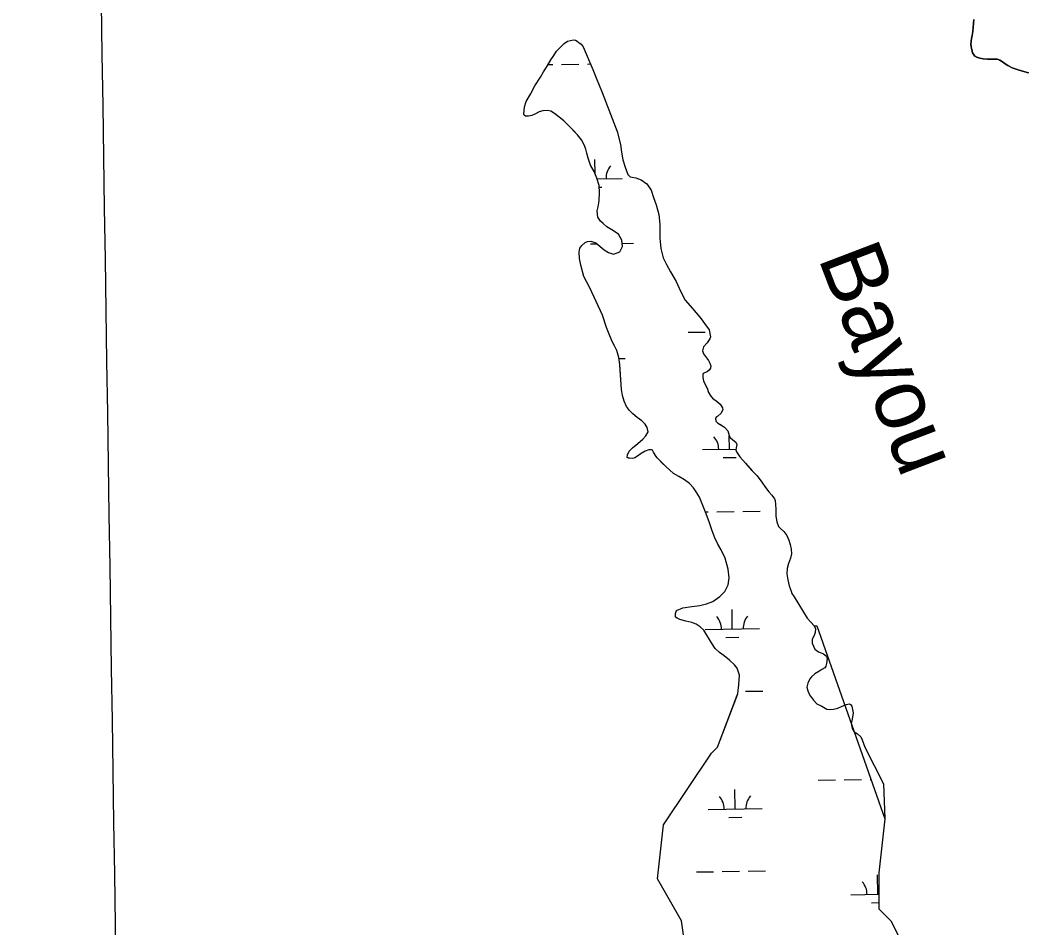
# Model space of a CAD drawing. Extents: x 3823584 to 3861785, y 301729 to 327625.
# Drawn here: x 3832860 to 3834718, y 313764 to 315442 of the extents above; entities that cross this region are included whole.
import ezdxf

# ---------------------------------------------------------------- set-up
doc = ezdxf.new("R2010")
doc.units = 0
for name, color, linetype in [('V-GRID-MAJR', 7, 'Continuous'), ('V-RIVR-IDEN', 7, 'Continuous'), ('V-TOPO-SHOR', 7, 'Continuous'), ('V-WETL-SWMP', 7, 'Continuous')]:
    doc.layers.add(name, color=color, linetype=linetype)

msp = doc.modelspace()

# ---------------------------------------------------------------- linework, layer by layer
at = {"layer": 'V-GRID-MAJR'}
msp.add_spline([(3833134.7290000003, 307237.467), (3833043.082, 313295.662), (3832951.406, 319355.783), (3832859.73, 325415.89900000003), (3832859.701, 325417.829)], degree=3, dxfattribs=at)
at = {"layer": 'V-TOPO-SHOR'}
for p, q in [((3834148.2605254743, 314097.8889411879), (3834184.037966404, 314191.527087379)), ((3834048.736592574, 313954.03293367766), (3834137.202533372, 314086.8229403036)), ((3834137.202533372, 314086.8229403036), (3834148.2605254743, 314097.8889411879)), ((3834455.48, 314029.759), (3834457.89626447, 313965.09997039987)), ((3834037.6785925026, 313854.43893368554), (3834048.736592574, 313954.03293367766)), ((3834457.89626447, 313965.09997039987), (3834446.8382643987, 313865.50697040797)), ((3834446.8382643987, 313865.50697040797), (3834446.838258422, 313799.11197107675)), ((3834081.9115499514, 313776.97793844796), (3834037.6785925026, 313854.43893368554)), ((3834446.838258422, 313799.11197107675), (3834468.954238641, 313776.97997329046)), ((3834092.9695340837, 313699.51694022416), (3834081.9115499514, 313776.97793844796)), ((3834468.954238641, 313776.97997329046), (3834491.0702168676, 313732.71597572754))]:
    msp.add_line(p, q, dxfattribs=at)
for points in [[(3834622.359, 315443.34), (3834621.632, 315435.681), (3834620.434, 315421.416), (3834619.183, 315413.48600000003), (3834618.171, 315408.2), (3834617.157, 315403.177), (3834616.9420000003, 315397.367), (3834617.796, 315390.248), (3834618.898, 315384.714), (3834619.717, 315381.554), (3834622.9220000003, 315377.093), (3834624.253, 315375.78500000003), (3834627.969, 315373.442), (3834633.2630000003, 315371.64), (3834639.341, 315370.634), (3834647.267, 315369.909), (3834653.335, 315370.224), (3834659.4050000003, 315370.278), (3834665.744, 315369.803), (3834670.247, 315367.994), (3834675.29, 315364.869), (3834680.332, 315361.482), (3834684.846, 315358.352), (3834693.328, 315354.201), (3834702.0670000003, 315350.842), (3834712.387, 315347.764), (3834723.235, 315344.688)], [(3833912.264, 314947.337), (3833901.623, 314967.917), (3833895.686, 314989.321), (3833893.486, 315001.601), (3833893.128, 315013.11100000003), (3833894.375, 315020.449), (3833897.992, 315025.712), (3833903.704, 315030.994), (3833908.133, 315033.124), (3833914.671, 315033.703), (3833923.598, 315030.115), (3833939.14, 315017.69), (3833947.295, 315012.525), (3833956.481, 315009.463), (3833968.216, 315014.012), (3833973.106, 315023.471), (3833971.6950000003, 315035.495), (3833965.326, 315046.169), (3833953.218, 315054.439), (3833944.012, 315060.118), (3833936.898, 315066.076), (3833932.148, 315070.745), (3833927.376, 315078.03), (3833925.969, 315089.532), (3833928.001, 315096.876), (3833929.74, 315107.88), (3833930.653, 315123.588), (3833930.02, 315136.402), (3833925.715, 315150.234), (3833920.38, 315162.22500000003), (3833913.741, 315173.942), (3833909.182, 315186.726), (3833907.271, 315196.128), (3833905.377, 315203.702), (3833902.168, 315211.78500000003), (3833897.1210000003, 315220.63800000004), (3833889.9760000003, 315229.998), (3833881.528, 315238.82300000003), (3833872.818, 315247.906), (3833864.376, 315255.946), (3833855.68, 315262.936), (3833846.988, 315269.666), (3833840.674, 315273.798), (3833833.599, 315275.04600000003), (3833825.4930000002, 315274.454), (3833818.705, 315272.566), (3833811.1520000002, 315268.576), (3833805.156, 315265.907), (3833799.413, 315264.29), (3833793.654, 315264.503), (3833791.023, 315266.313), (3833790.4820000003, 315268.4), (3833791.6780000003, 315281.755), (3833794.994, 315291.727), (3833802.7290000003, 315305.137), (3833810.708, 315320.902), (3833821.562, 315336.695), (3833827.235, 315346.425), (3833833.949, 315357.20900000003), (3833840.65, 315369.041), (3833845.8170000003, 315376.934), (3833851.2460000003, 315384.569), (3833858.764, 315392.744), (3833865.252, 315399.079), (3833871.4990000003, 315403.058), (3833882.204, 315405.76300000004), (3833885.87, 315405.272), (3833889.288, 315403.47000000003), (3833892.452, 315400.619), (3833896.665, 315397.514), (3833900.103, 315393.094), (3833918.253, 315351.123), (3833924.143, 315335.474), (3833935.6240000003, 315308.358), (3833963.186, 315236.375), (3833969.4080000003, 315212.356), (3833971.363, 315197.719), (3833973.835, 315184.135), (3833977.6180000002, 315170.039), (3833982.961, 315157.001), (3833987.184, 315152.588), (3833990.59, 315152.094), (3833997.406, 315150.843), (3834007.379, 315147.003), (3834017.648, 315139.503), (3834025.6010000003, 315127.534), (3834030.4220000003, 315114.493), (3834034.984, 315100.925), (3834039.848, 315082.65), (3834042.091, 315065.13800000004), (3834042.1890000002, 315053.626), (3834041.79, 315038.971), (3834044.049, 315019.627), (3834048.378, 315002.656), (3834053.98, 314990.14400000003), (3834061.42, 314976.601), (3834072.301, 314958.64), (3834080.3030000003, 314940.914), (3834088.816, 314924.242), (3834102.294, 314908.656), (3834109.163, 314900.866)], [(3834184.037966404, 314191.527087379), (3834185.793, 314196.876), (3834188.009, 314213.117), (3834188.906, 314230.918), (3834184.6070000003, 314243.964), (3834180.108, 314250.206), (3834170.873, 314259.023), (3834160.603, 314266.787), (3834151.915, 314272.992), (3834144.2660000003, 314280.252), (3834137.112, 314290.658), (3834123.046, 314314.087), (3834116.7120000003, 314320.575), (3834109.345, 314325.222), (3834100.946, 314328.29), (3834090.194, 314331.077), (3834079.1780000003, 314334.125), (3834073.667, 314336.17100000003), (3834070.769, 314338.501), (3834070.9760000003, 314344.783), (3834072.7600000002, 314350.554), (3834084.231, 314355.623), (3834101.217, 314358.121), (3834115.852, 314360.077), (3834128.39, 314362.801), (3834139.865, 314367.085), (3834152.869, 314376.355), (3834162.21, 314385.591), (3834168.123, 314397.938), (3834170.1070000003, 314410.777), (3834168.397, 314427.24700000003), (3834162.468, 314447.607), (3834155.54, 314462.463), (3834149.169, 314473.135), (3834143.311, 314484.86), (3834138.757, 314497.641), (3834133.119, 314514.341), (3834126.4220000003, 314532.601), (3834120.273, 314547.985), (3834115.201, 314559.978), (3834109.36, 314569.87), (3834104.061, 314577.415), (3834096.93, 314585.203), (3834087.45, 314592.449), (3834077.196, 314598.38), (3834067.468, 314603.791), (3834059.56, 314610.527), (3834053.494, 314616.233), (3834045.843, 314623.755), (3834039.775, 314629.723), (3834036.8710000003, 314632.576), (3834033.954, 314636.999), (3834030.4990000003, 314643.512), (3834028.115, 314646.893), (3834026.8030000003, 314647.405), (3834021.83, 314647.362), (3834014.787, 314644.94800000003), (3834007.2320000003, 314640.958), (3834000.472, 314635.93), (3833995.526, 314633.01), (3833993.961, 314632.473), (3833991.614, 314631.406), (3833986.113, 314632.146), (3833984.282, 314632.129), (3833983.494, 314632.645), (3833981.653, 314633.678), (3833981.876, 314638.128), (3833985.22, 314644.958), (3833991.708, 314651.032), (3834001.322, 314659.224), (3834010.411, 314667.412), (3834016.112, 314673.741), (3834020.4990000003, 314681.105), (3834018.336, 314689.199), (3834014.8850000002, 314694.925), (3834008.551, 314701.413), (3834000.128, 314707.358), (3833991.958, 314714.092), (3833985.89, 314720.058), (3833980.332, 314727.601), (3833976.059, 314737.507), (3833972.832, 314747.946), (3833970.903, 314759.441), (3833969.7, 314777.748), (3833968.775, 314794.224), (3833968.1580000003, 314805.21), (3833966.217, 314818.27400000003), (3833962.182, 314831.06200000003), (3833958.18, 314840.186), (3833954.461, 314846.696), (3833949.392, 314858.165), (3833943.502, 314873.816), (3833935.72, 314896.77400000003), (3833912.264, 314947.337)], [(3834109.163, 314900.866), (3834112.6, 314896.708), (3834118.156, 314889.69), (3834124.247, 314881.107), (3834132.9790000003, 314869.406), (3834135.707, 314856.346), (3834134.429, 314852.672), (3834129.52, 314845.306), (3834122.5160000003, 314838.181), (3834120.486, 314830.837), (3834122.627, 314825.36), (3834126.3310000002, 314820.42), (3834131.628, 314812.878), (3834134.286, 314808.19), (3834136.16, 314803.23600000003), (3834135.6720000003, 314798.783), (3834133.35, 314795.101), (3834129.19, 314791.925), (3834124.236, 314789.788), (3834122.151, 314788.726), (3834121.642, 314787.151), (3834121.17, 314781.127), (3834122.526, 314775.38300000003), (3834124.396, 314770.951), (3834129.448, 314761.57300000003), (3834131.869, 314753.746), (3834136.117, 314746.717), (3834139.2830000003, 314743.342), (3834148.765, 314736.096), (3834153.2460000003, 314732.211), (3834158.014, 314725.446), (3834158.307, 314721.787), (3834154.4420000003, 314714.688), (3834148.988, 314709.933), (3834146.381, 314708.602), (3834144.569, 314706.494), (3834145.142, 314700.479), (3834146.461, 314699.183), (3834148.569, 314697.63), (3834155.671, 314693.244), (3834161.723, 314689.371), (3834167.795, 314682.881), (3834170.224, 314674.005), (3834172.088, 314670.357), (3834176.575, 314665.94800000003), (3834182.1010000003, 314662.069), (3834184.235, 314657.377), (3834182.715, 314651.608), (3834182.486, 314647.68200000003), (3834183.301, 314644.02400000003), (3834189.9220000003, 314634.663), (3834200.223, 314623.237), (3834206.04, 314616.22000000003), (3834212.384, 314608.688), (3834221.6210000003, 314599.347), (3834230.616, 314587.911), (3834237.239, 314578.28500000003), (3834243.328, 314569.962), (3834248.611, 314563.99), (3834253.639, 314557.23), (3834254.977, 314553.84), (3834255.824, 314546.521), (3834256.16, 314537.626), (3834256.271, 314524.808), (3834258.19, 314514.357), (3834261.401, 314506.011), (3834264.8340000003, 314502.376), (3834270.9020000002, 314496.41000000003), (3834276.72, 314489.134), (3834280.196, 314480.528), (3834282.616, 314472.699), (3834284.785, 314463.82300000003), (3834285.379, 314455.454), (3834283.62, 314447.066), (3834279.778, 314437.352), (3834277.236, 314428.433), (3834276.8000000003, 314418.226), (3834278.199, 314407.509), (3834280.91, 314396.282), (3834284.398, 314386.105), (3834286.006, 314381.933), (3834290.241, 314375.951), (3834314.125, 314336.64400000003), (3834320.7320000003, 314329.11100000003), (3834327.0700000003, 314322.101), (3834329.475, 314316.367), (3834329.004, 314310.081), (3834326.96, 314304.308), (3834323.353, 314297.474), (3834323.417, 314290.148), (3834328.481, 314279.202), (3834335.066, 314274.02400000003), (3834344.255, 314270.44), (3834350.049, 314266.041), (3834351.13, 314261.863), (3834350.163, 314252.436), (3834348.6380000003, 314247.451), (3834346.565, 314244.818), (3834341.099, 314241.369), (3834335.6350000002, 314237.92), (3834328.348, 314233.148)], [(3834328.348, 314233.148), (3834322.376, 314227.864), (3834319.265, 314224.436), (3834315.151, 314216.029), (3834313.639, 314208.951), (3834315.27, 314201.902), (3834318.735, 314194.605), (3834325.622, 314184.457), (3834332.217, 314178.233), (3834341.1520000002, 314173.601), (3834350.6180000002, 314168.186), (3834355.335, 314167.44), (3834362.918, 314168.03), (3834371.012, 314169.928), (3834379.094, 314173.662), (3834387.177, 314176.869), (3834391.617, 314177.692), (3834394.505, 314176.67), (3834396.6240000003, 314173.549), (3834399.082, 314161.534), (3834397.612, 314149.745), (3834395.59, 314141.357), (3834397.235, 314132.47500000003), (3834401.214, 314126.228), (3834407.264, 314122.353), (3834413.068, 314116.91000000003), (3834415.992, 314111.44), (3834420.8170000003, 314097.874), (3834455.48, 314029.759)]]:
    msp.add_lwpolyline(points, dxfattribs=at)
at = {"layer": 'V-WETL-SWMP'}
for p, q in [((3833835.4841020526, 315359.9205757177), (3833844.4187046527, 315360.05833587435)), ((3833860.4167966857, 315360.30500601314), (3833892.4129807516, 315360.79834629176)), ((3833908.4110727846, 315361.04501643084), (3833913.92574666, 315361.13004565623)), ((3833922.3915609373, 315157.70622458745), (3833921.9764460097, 315184.6291869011)), ((3833926.1965552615, 315148.68997681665), (3833972.5254879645, 315149.4043097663)), ((3833930.1724266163, 315133.31844562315), (3833934.767915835, 315133.3893021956)), ((3833913.5398525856, 315028.409555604), (3833925.5008429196, 315028.5939787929)), ((3833972.421079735, 315029.31742889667), (3833993.53031275, 315029.6429062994)), ((3834093.9885066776, 314864.9980927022), (3834125.9846907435, 314865.4914329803)), ((3833966.4655189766, 314816.59633272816), (3833977.6542677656, 314816.76884893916)), ((3834170.7369421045, 314648.91263512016), (3834170.353950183, 314673.75220693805)), ((3834120.742904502, 314648.1417909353), (3834182.5672878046, 314649.0950439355)), ((3834158.9762695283, 314633.29846652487), (3834182.9734075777, 314633.6684717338)), ((3834126.348926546, 314532.78250897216), (3834131.113470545, 314532.8559721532)), ((3834147.111562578, 314533.1026422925), (3834179.1077466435, 314533.59598257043)), ((3834195.1058386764, 314533.84265270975), (3834227.1020227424, 314534.3359929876)), ((3834175.8657219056, 314316.27717429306), (3834175.310717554, 314352.27289561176)), ((3834125.8716843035, 314315.50633010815), (3834225.8597595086, 314317.0480184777)), ((3834164.10504933, 314300.6630056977), (3834188.102187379, 314301.0330109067)), ((3834200.234618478, 314201.2071918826), (3834232.230802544, 314201.7005321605)), ((3834389.7719006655, 314157.69409617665), (3834390.0606200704, 314157.69854786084)), ((3834334.7857882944, 314036.7610095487), (3834366.7819723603, 314037.25434982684)), ((3834382.7800643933, 314037.5010199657), (3834414.776248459, 314037.9943602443)), ((3834430.7743404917, 314038.24103038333), (3834432.1277123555, 314038.26189764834)), ((3834180.994501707, 313983.6417134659), (3834180.4394973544, 314019.6374347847)), ((3834131.000464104, 313982.87086928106), (3834230.9885393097, 313984.4125576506)), ((3834169.2338291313, 313968.0275448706), (3834193.2309671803, 313968.39755007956)), ((3834109.3748460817, 313867.0917102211), (3834141.3710301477, 313867.5850504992)), ((3834157.36912218, 313867.8317206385), (3834189.365306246, 313868.3250609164)), ((3834205.3633982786, 313868.57173105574), (3834237.3595823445, 313869.06507133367)), ((3834444.894718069, 313825.8294795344), (3834444.339713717, 313861.8252008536)), ((3834394.9006804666, 313825.05863534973), (3834446.838260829, 313825.8594464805)), ((3834433.1340454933, 313810.2153109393), (3834446.83825944, 313810.4266124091))]:
    msp.add_line(p, q, dxfattribs=at)
for points in [[(3834723.235, 315344.688), (3834712.387, 315347.764), (3834702.0670000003, 315350.843), (3834693.328, 315354.2), (3834684.846, 315358.352), (3834680.332, 315361.481), (3834675.289, 315364.869), (3834670.247, 315367.994), (3834665.744, 315369.803), (3834659.406, 315370.277), (3834653.335, 315370.22500000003), (3834647.267, 315369.91000000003), (3834639.342, 315370.634), (3834633.2630000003, 315371.639), (3834627.969, 315373.441), (3834624.253, 315375.78500000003), (3834622.9220000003, 315377.094), (3834619.717, 315381.554), (3834618.898, 315384.714), (3834617.796, 315390.248), (3834616.943, 315397.367), (3834617.1580000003, 315403.176), (3834618.171, 315408.2), (3834619.182, 315413.487), (3834620.434, 315421.416), (3834621.633, 315435.68), (3834622.359, 315443.341)], [(3833939.1410000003, 315017.689), (3833947.296, 315012.525), (3833956.48, 315009.463), (3833968.216, 315014.011), (3833973.1070000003, 315023.472), (3833971.696, 315035.496), (3833965.326, 315046.17), (3833953.219, 315054.44), (3833944.0130000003, 315060.118), (3833936.898, 315066.076), (3833932.148, 315070.745), (3833927.376, 315078.031), (3833925.97, 315089.532), (3833928.001, 315096.876), (3833929.739, 315107.88), (3833930.653, 315123.587), (3833930.02, 315136.403), (3833925.716, 315150.234), (3833920.381, 315162.22500000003), (3833913.74, 315173.943), (3833909.183, 315186.726), (3833907.272, 315196.129), (3833905.376, 315203.701), (3833902.167, 315211.78500000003), (3833897.1210000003, 315220.63800000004), (3833889.9760000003, 315229.99700000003), (3833872.8170000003, 315247.906), (3833864.375, 315255.945), (3833855.681, 315262.936), (3833846.989, 315269.665), (3833840.6750000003, 315273.798), (3833833.599, 315275.04600000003), (3833825.4930000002, 315274.454), (3833818.7060000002, 315272.565), (3833811.1520000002, 315268.576), (3833805.156, 315265.908), (3833799.414, 315264.29), (3833793.6550000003, 315264.502), (3833791.023, 315266.31200000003), (3833790.4820000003, 315268.4), (3833791.677, 315281.755), (3833794.994, 315291.726), (3833802.73, 315305.136), (3833810.707, 315320.903), (3833821.562, 315336.695), (3833827.236, 315346.424), (3833833.948, 315357.20900000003), (3833840.65, 315369.041), (3833845.816, 315376.934), (3833851.2460000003, 315384.569), (3833858.765, 315392.744), (3833865.252, 315399.079), (3833871.498, 315403.05700000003), (3833882.203, 315405.764), (3833885.87, 315405.272), (3833889.287, 315403.469), (3833892.451, 315400.618), (3833896.664, 315397.514), (3833900.103, 315393.09500000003), (3833918.253, 315351.123), (3833924.142, 315335.473), (3833935.6240000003, 315308.359), (3833963.186, 315236.376), (3833969.4080000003, 315212.356), (3833971.364, 315197.72000000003), (3833973.835, 315184.135), (3833977.6180000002, 315170.038), (3833982.961, 315157), (3833987.185, 315152.588), (3833990.591, 315152.094), (3833997.4050000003, 315150.843), (3834007.38, 315147.003), (3834017.649, 315139.503), (3834025.6, 315127.534), (3834030.421, 315114.492), (3834034.984, 315100.925), (3834039.849, 315082.65), (3834042.091, 315065.13800000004), (3834042.1890000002, 315053.626), (3834041.791, 315038.97000000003), (3834044.048, 315019.627), (3834048.379, 315002.656), (3834053.98, 314990.14400000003), (3834061.421, 314976.601), (3834072.302, 314958.639), (3834080.302, 314940.915), (3834088.8170000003, 314924.241), (3834102.294, 314908.656), (3834109.163, 314900.865), (3834112.6, 314896.708), (3834118.1550000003, 314889.69), (3834124.2460000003, 314881.107), (3834132.98, 314869.407), (3834135.707, 314856.347), (3834134.43, 314852.673), (3834129.521, 314845.305), (3834122.517, 314838.181), (3834120.486, 314830.837), (3834122.626, 314825.36100000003), (3834126.3310000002, 314820.42100000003), (3834131.628, 314812.878)], [(3834184.92, 314193.835), (3834185.793, 314196.876), (3834188.0100000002, 314213.117), (3834188.9050000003, 314230.918), (3834184.608, 314243.964), (3834180.1070000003, 314250.205), (3834170.8740000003, 314259.023), (3834160.603, 314266.786), (3834151.916, 314272.992), (3834144.2660000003, 314280.253), (3834137.113, 314290.658), (3834123.046, 314314.088), (3834116.711, 314320.576), (3834109.345, 314325.223), (3834100.946, 314328.291), (3834090.1950000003, 314331.078), (3834079.179, 314334.124), (3834073.667, 314336.17100000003), (3834070.769, 314338.501), (3834070.977, 314344.783), (3834072.7600000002, 314350.554), (3834084.23, 314355.623), (3834101.216, 314358.12200000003), (3834115.852, 314360.078), (3834128.389, 314362.801), (3834139.865, 314367.085), (3834152.869, 314376.354), (3834162.21, 314385.591), (3834168.123, 314397.939), (3834170.108, 314410.777), (3834168.398, 314427.24700000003), (3834162.468, 314447.606), (3834155.539, 314462.462), (3834149.168, 314473.135), (3834143.312, 314484.86), (3834138.756, 314497.642), (3834133.119, 314514.341), (3834126.4220000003, 314532.60000000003), (3834120.273, 314547.985), (3834115.2, 314559.978), (3834109.36, 314569.871), (3834104.062, 314577.414), (3834096.931, 314585.204), (3834087.45, 314592.449), (3834077.1950000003, 314598.38), (3834067.468, 314603.792), (3834059.561, 314610.528), (3834053.494, 314616.233), (3834036.8710000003, 314632.576), (3834033.955, 314637), (3834030.4990000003, 314643.512), (3834028.115, 314646.893), (3834026.802, 314647.405), (3834021.8310000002, 314647.363), (3834014.787, 314644.94800000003), (3834007.233, 314640.95900000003), (3834000.472, 314635.93), (3833995.526, 314633.01), (3833993.96, 314632.473), (3833991.615, 314631.407), (3833986.114, 314632.145), (3833984.282, 314632.129), (3833981.6520000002, 314633.677), (3833981.876, 314638.127), (3833985.22, 314644.958), (3833991.7090000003, 314651.032), (3834001.321, 314659.22500000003), (3834010.41, 314667.413), (3834016.112, 314673.741), (3834020.498, 314681.105), (3834018.336, 314689.19800000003), (3834014.886, 314694.925), (3834008.551, 314701.413), (3834000.127, 314707.359), (3833991.9590000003, 314714.093), (3833985.89, 314720.059), (3833980.3310000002, 314727.60000000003), (3833976.06, 314737.507), (3833972.832, 314747.946), (3833970.9020000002, 314759.442), (3833969.7, 314777.748), (3833968.1580000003, 314805.20900000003), (3833966.216, 314818.275), (3833962.182, 314831.06200000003), (3833958.18, 314840.186), (3833954.461, 314846.696), (3833949.392, 314858.165), (3833943.503, 314873.815), (3833935.72, 314896.77400000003), (3833912.264, 314947.336), (3833901.623, 314967.917), (3833895.685, 314989.322), (3833893.487, 315001.601), (3833893.128, 315013.11100000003), (3833894.3740000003, 315020.44800000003), (3833897.992, 315025.712), (3833903.704, 315030.994), (3833908.134, 315033.124), (3833914.67, 315033.703), (3833923.597, 315030.116), (3833939.1410000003, 315017.689)], [(3834131.628, 314812.878), (3834134.285, 314808.19), (3834136.159, 314803.235), (3834135.673, 314798.783), (3834133.349, 314795.10000000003), (3834129.19, 314791.924), (3834124.237, 314789.789), (3834122.1520000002, 314788.72500000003), (3834121.642, 314787.15), (3834121.17, 314781.128), (3834122.5270000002, 314775.38300000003), (3834124.397, 314770.951), (3834129.448, 314761.574), (3834131.869, 314753.745), (3834136.116, 314746.717), (3834139.284, 314743.342), (3834148.765, 314736.096), (3834153.2460000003, 314732.21), (3834158.014, 314725.447), (3834158.307, 314721.786), (3834154.4420000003, 314714.689), (3834148.988, 314709.933), (3834146.382, 314708.602), (3834144.569, 314706.494), (3834145.143, 314700.48), (3834146.4620000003, 314699.183), (3834148.569, 314697.631), (3834161.722, 314689.37), (3834167.795, 314682.88), (3834170.225, 314674.005), (3834172.088, 314670.357), (3834176.574, 314665.947), (3834182.1010000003, 314662.069), (3834184.235, 314657.378), (3834182.714, 314651.608), (3834182.485, 314647.681), (3834183.301, 314644.025), (3834189.9220000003, 314634.662), (3834200.224, 314623.237), (3834212.384, 314608.68700000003), (3834221.6210000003, 314599.346), (3834230.615, 314587.91000000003), (3834237.238, 314578.28500000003), (3834243.327, 314569.963), (3834248.611, 314563.99), (3834253.64, 314557.23), (3834254.977, 314553.84), (3834255.824, 314546.52), (3834256.161, 314537.627), (3834256.27, 314524.80700000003), (3834258.19, 314514.357), (3834261.401, 314506.011), (3834264.8340000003, 314502.377), (3834270.9020000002, 314496.411), (3834276.721, 314489.134), (3834280.1950000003, 314480.529), (3834282.617, 314472.699), (3834284.785, 314463.822), (3834285.38, 314455.454), (3834283.62, 314447.066), (3834279.7770000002, 314437.352), (3834277.237, 314428.434), (3834276.8000000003, 314418.22500000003), (3834278.199, 314407.509), (3834280.911, 314396.281), (3834284.399, 314386.106), (3834286.005, 314381.933), (3834290.242, 314375.951), (3834314.125, 314336.64400000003), (3834320.731, 314329.112), (3834327.0700000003, 314322.102), (3834332.194, 314321.994), (3834457.896, 313965.10000000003), (3834446.838, 313865.507), (3834446.838, 313799.112), (3834468.954, 313776.98), (3834491.0700000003, 313732.716)], [(3834402.599, 313312.21), (3834380.483, 313345.408), (3834336.25, 313367.54), (3834280.9590000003, 313378.606), (3834247.784, 313400.737), (3834303.075, 313445.001), (3834292.017, 313467.13300000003), (3834192.4930000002, 313489.265), (3834137.202, 313511.396), (3834104.0270000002, 313544.594), (3834092.969, 313577.792), (3834081.911, 313633.121), (3834092.969, 313699.517), (3834081.911, 313776.978), (3834037.6780000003, 313854.439), (3834048.736, 313954.033), (3834137.202, 314086.82300000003), (3834148.2600000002, 314097.889), (3834184.92, 314193.835)]]:
    msp.add_lwpolyline(points, dxfattribs=at)
for centre, radius, start, end in [((3833977.760478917, 315149.95988625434), 35.246287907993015, 140.1115349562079, 181.65519328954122), ((3834115.493273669, 314648.5357079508), 35.24628790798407, 0.1115373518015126, 41.65519568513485), ((3834120.62205347, 314315.90024712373), 35.24628790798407, 0.1115373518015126, 41.65519568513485), ((3834231.0947504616, 314317.6035949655), 35.246287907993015, 140.1115349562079, 181.65519328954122), ((3834125.750833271, 313983.26478629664), 35.24628790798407, 0.1115373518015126, 41.65519568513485), ((3834236.223530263, 313984.9681341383), 35.246287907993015, 140.1115349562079, 181.65519328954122), ((3834389.651049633, 313825.4525523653), 35.24628790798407, 0.1115373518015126, 41.65519568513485)]:
    msp.add_arc(centre, radius, start, end, dxfattribs=at)

# ---------------------------------------------------------------- texts
at = {"layer": 'V-RIVR-IDEN'}
msp.add_text('Bayou', height=115.99976600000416, rotation=290.92123622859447, dxfattribs=at).set_placement((3834333.773293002, 315002.86396889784))

doc.saveas('drawing.dxf')
